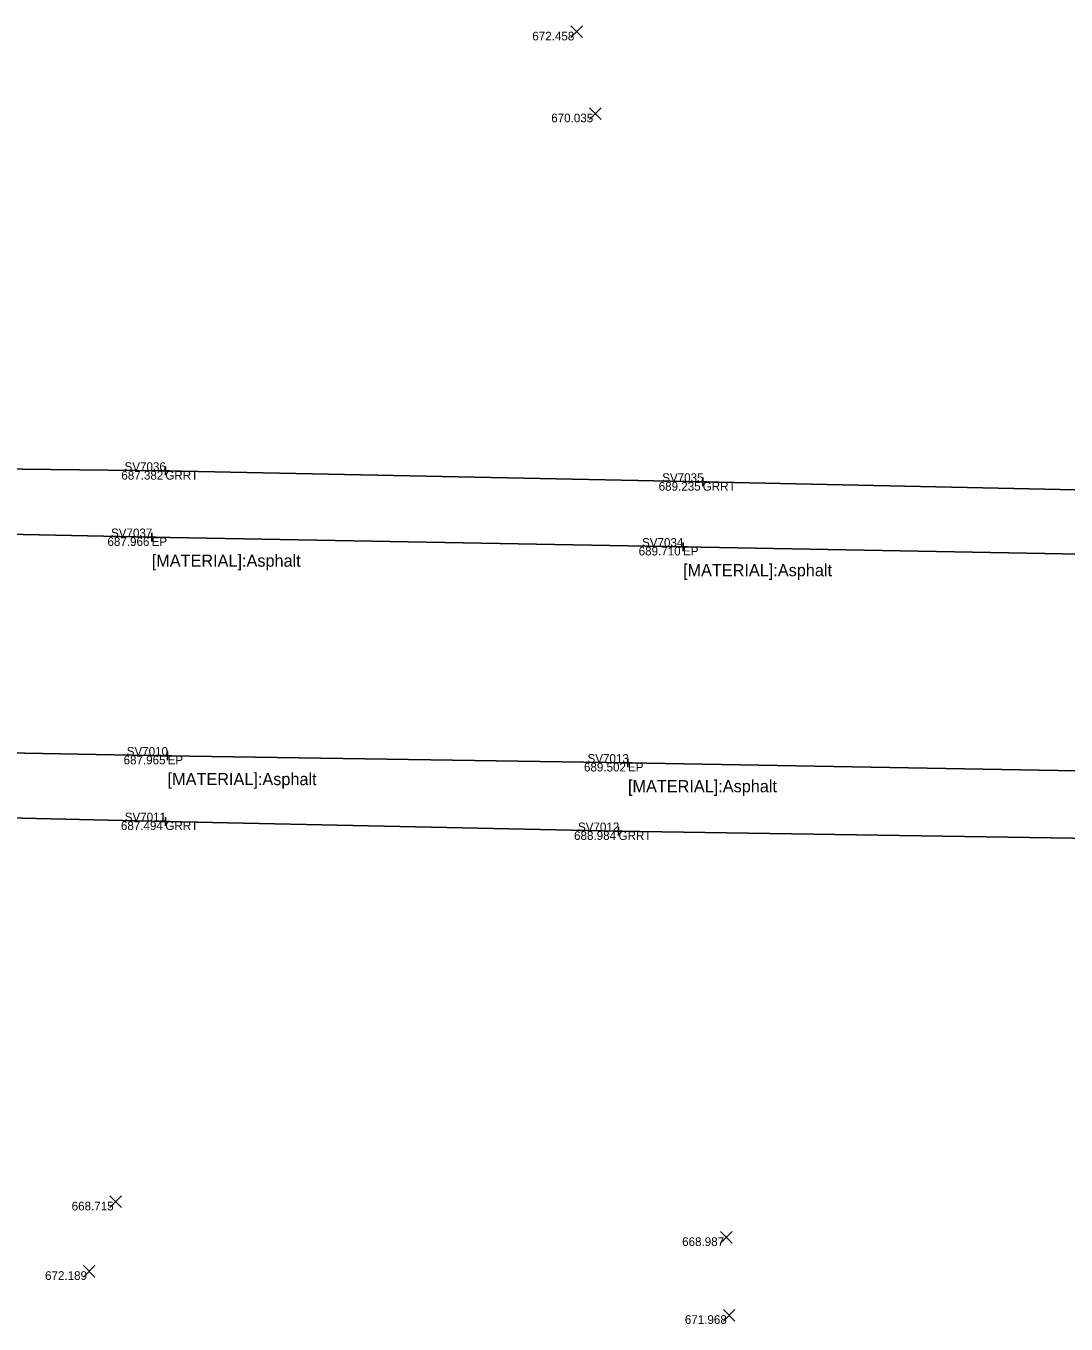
# Model space of a CAD drawing. Extents: x 1660019 to 1662995, y 619975 to 620342.
# Drawn here: x 1660840.7 to 1660960.5, y 620163.7 to 620313.4 of the extents above; entities that cross this region are included whole.
import ezdxf

# ---------------------------------------------------------------- set-up
doc = ezdxf.new("R2010")
doc.units = 0
for name, color, linetype in [('BR_X_Rail_Object', 7, 'Continuous'), ('PV_X_EOP', 7, 'Continuous'), ('RD_P_GR_Lt', 7, 'Continuous'), ('RD_P_GR_Rt', 7, 'Continuous'), ('RD_X_GR_Bar', 7, 'Continuous'), ('RD_X_GR_Rt', 7, 'Continuous'), ('RD_X_Wall', 7, 'Continuous'), ('SV_X_Text', 7, 'Continuous')]:
    doc.layers.add(name, color=color, linetype=linetype)

msp = doc.modelspace()

# ---------------------------------------------------------------- linework, layer by layer
at = {"layer": 'PV_X_EOP'}
for points in [[(1661208.92, 620246.9), (1661156.94, 620248.21), (1661087.29, 620250.6), (1661037.39, 620250.48), (1660981.01, 620252.16), (1660916.41, 620253.34), (1660855.2, 620254.44), (1660801.44, 620255.57), (1660749.64, 620256.49), (1660700.03, 620257.78), (1660643.44, 620258.64), (1660593.17, 620259.57)], [(1660597.37, 620234.1), (1660651.64, 620233.44), (1660703.42, 620232.61), (1660757.32, 620231.35), (1660809.76, 620230.12), (1660857.03, 620229.26), (1660910.07, 620228.44), (1660968.25, 620227.38), (1661028.27, 620226.15), (1661081.58, 620225.11), (1661140.41, 620223.53), (1661201.71, 620222.7)]]:
    msp.add_lwpolyline(points, dxfattribs=at)
at = {"layer": 'RD_P_GR_Lt'}
for p, q in [((1660856.27, 620262.08), (1660857.27, 620262.08)), ((1660856.77, 620262.58), (1660856.77, 620261.58)), ((1660856.77, 620262.08), (1660856.77, 620262.08)), ((1660918.18, 620260.81), (1660919.18, 620260.81)), ((1660918.68, 620261.31), (1660918.68, 620260.31)), ((1660918.68, 620260.81), (1660918.68, 620260.81)), ((1660855.2, 620254.94), (1660855.2, 620253.94)), ((1660854.7, 620254.44), (1660855.7, 620254.44)), ((1660855.2, 620254.44), (1660855.2, 620254.44)), ((1660915.91, 620253.34), (1660916.91, 620253.34)), ((1660916.41, 620253.84), (1660916.41, 620252.84)), ((1660916.41, 620253.34), (1660916.41, 620253.34)), ((1660856.53, 620229.26), (1660857.53, 620229.26)), ((1660857.03, 620229.76), (1660857.03, 620228.76)), ((1660857.03, 620229.26), (1660857.03, 620229.26)), ((1660909.57, 620228.44), (1660910.57, 620228.44)), ((1660910.07, 620228.94), (1660910.07, 620227.94)), ((1660910.07, 620228.44), (1660910.07, 620228.44)), ((1660856.27, 620221.69), (1660857.27, 620221.69)), ((1660856.77, 620222.19), (1660856.77, 620221.19)), ((1660856.77, 620221.69), (1660856.77, 620221.69)), ((1660908.48, 620220.55), (1660909.48, 620220.55)), ((1660908.98, 620221.05), (1660908.98, 620220.05)), ((1660908.98, 620220.55), (1660908.98, 620220.55))]:
    msp.add_line(p, q, dxfattribs=at)
at = {"layer": 'RD_P_GR_Rt'}
for p, q in [((1660903.48, 620312.04), (1660904.82, 620313.38)), ((1660903.48, 620313.38), (1660904.82, 620312.04)), ((1660905.64, 620302.6), (1660906.97, 620303.94)), ((1660905.64, 620303.94), (1660906.97, 620302.6)), ((1660850.38, 620177.18), (1660851.72, 620178.51)), ((1660850.38, 620178.51), (1660851.72, 620177.18)), ((1660920.74, 620173.07), (1660922.07, 620174.41)), ((1660920.74, 620174.41), (1660922.07, 620173.07)), ((1660847.33, 620169.16), (1660848.66, 620170.5)), ((1660847.33, 620170.5), (1660848.66, 620169.16)), ((1660921.06, 620164.09), (1660922.39, 620165.42)), ((1660921.06, 620165.42), (1660922.39, 620164.09))]:
    msp.add_line(p, q, dxfattribs=at)
at = {"layer": 'RD_X_GR_Rt'}
for points in [[(1661224.69, 620250.79), (1661156.18, 620253.35), (1661087.54, 620257.19), (1661037.26, 620258.5), (1660981.37, 620259.47), (1660918.68, 620260.81), (1660856.77, 620262.08), (1660800.7, 620262.74), (1660750.31, 620264.54), (1660700.27, 620265.16), (1660644.43, 620266.52), (1660592.86, 620267.53)], [(1660596.86, 620226.32), (1660650.68, 620225.81), (1660702.7, 620224.83), (1660759.05, 620223.97), (1660808.86, 620222.78), (1660856.77, 620221.69), (1660908.98, 620220.55), (1660971.26, 620219.59), (1661027.54, 620217.92), (1661083.51, 620217.29), (1661139.61, 620218.11), (1661215.13, 620218.24)]]:
    msp.add_lwpolyline(points, dxfattribs=at)

# ---------------------------------------------------------------- texts
at = {"layer": 'BR_X_Rail_Object'}
for s, p in [('GRRT', (1660856.77, 620261.08)), ('GRRT', (1660918.68, 620259.81)), ('EP', (1660855.2, 620253.44)), ('EP', (1660916.41, 620252.34)), ('EP', (1660857.03, 620228.26)), ('EP', (1660910.07, 620227.44)), ('GRRT', (1660856.77, 620220.69)), ('GRRT', (1660908.98, 620219.55))]:
    msp.add_text(s, height=1, dxfattribs=at).set_placement(p)
at = {"layer": 'RD_X_GR_Bar'}
for s, p in [('672.458', (1660899.05, 620311.71)), ('670.035', (1660901.23, 620302.27)), ('687.382', (1660851.7, 620261.08)), ('689.235', (1660913.61, 620259.81)), ('687.966', (1660850.1, 620253.44)), ('689.710', (1660911.3, 620252.34)), ('687.965', (1660851.96, 620228.26)), ('689.502', (1660905, 620227.44)), ('687.494', (1660851.65, 620220.69)), ('688.984', (1660903.86, 620219.55)), ('668.715', (1660845.98, 620176.84)), ('668.987', (1660916.31, 620172.74)), ('672.189', (1660842.91, 620168.83)), ('671.968', (1660916.62, 620163.76))]:
    msp.add_text(s, height=1, dxfattribs=at).set_placement(p)
at = {"layer": 'RD_X_Wall'}
for s, p in [('SV7036', (1660852.07, 620262.08)), ('SV7035', (1660914.01, 620260.81)), ('SV7037', (1660850.51, 620254.44)), ('SV7034', (1660911.69, 620253.34)), ('SV7010', (1660852.32, 620229.26)), ('SV7013', (1660905.41, 620228.44)), ('SV7011', (1660852.09, 620221.69)), ('SV7012', (1660904.31, 620220.55))]:
    msp.add_text(s, height=1, dxfattribs=at).set_placement(p)
at = {"layer": 'SV_X_Text'}
for p in [(1660855.2, 620251.04), (1660916.41, 620249.94), (1660857.03, 620225.86), (1660910.07, 620225.04)]:
    msp.add_text('[MATERIAL]:Asphalt', height=1.4, dxfattribs=at).set_placement(p)

doc.saveas('drawing.dxf')
